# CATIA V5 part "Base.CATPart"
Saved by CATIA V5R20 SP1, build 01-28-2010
Part number: Base
Bounding box of the stored display mesh (mm): x -23.876 to 23.876, y 0 to 88.9, z 0 to 54.102
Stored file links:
  D:\v5_r20\psrt_files_downloaded\c13-catia-v5r20-prt\c13-catia-v5r20-figr-13-43\Part & Asm files\Base.CATPart
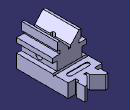
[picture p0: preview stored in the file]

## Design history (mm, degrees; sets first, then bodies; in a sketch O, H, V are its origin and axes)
Body1 (main body)
  Sketch1 on xy-plane, origin (0, 0, 0), H (1, 0, 0), V (0, 1, 0)
    line L1 (-23.876, 0) -> (23.876, 0)
    point P1 (-23.876, 0)
    point P2 (23.876, 0)
    construction line L2 (-23.876, 50.8) -> (23.876, 50.8)
    point P3 (-23.876, 50.8)
    point P4 (23.876, 50.8)
    line L3 (23.876, 0) -> (23.876, 72.898)
    point P5 (23.876, 72.898)
    line L4 (23.876, 72.898) -> (13.462, 72.898)
    point P6 (13.462, 72.898)
    line L5 (13.462, 72.898) -> (13.462, 77.724)
    point P7 (13.462, 77.724)
    line L6 (13.462, 77.724) -> (16.51, 77.724)
    point P8 (16.51, 77.724)
    line L7 (16.51, 77.724) -> (16.51, 88.9)
    point P9 (16.51, 88.9)
    line L8 (16.51, 88.9) -> (13.462, 88.9)
    point P10 (13.462, 88.9)
    line L9 (13.462, 88.9) -> (1.778, 77.724)
    point P11 (1.778, 77.724)
    line L10 (1.778, 77.724) -> (1.778, 72.898)
    point P12 (1.778, 72.898)
    line L11 (1.778, 72.898) -> (0, 72.898)
    point P13 (0, 72.898)
    point P14 (0, 72.898)
    point P15 (-1.778, 72.898)
    line L12 (-1.778, 72.898) -> (0, 72.898)
    point P16 (-1.778, 77.724)
    line L13 (-1.778, 77.724) -> (-1.778, 72.898)
    point P17 (-13.462, 88.9)
    line L14 (-13.462, 88.9) -> (-1.778, 77.724)
    point P18 (-16.51, 88.9)
    line L15 (-16.51, 88.9) -> (-13.462, 88.9)
    point P19 (-16.51, 77.724)
    line L16 (-16.51, 77.724) -> (-16.51, 88.9)
    point P20 (-13.462, 77.724)
    line L17 (-13.462, 77.724) -> (-16.51, 77.724)
    point P21 (-13.462, 72.898)
    line L18 (-13.462, 72.898) -> (-13.462, 77.724)
    point P22 (-23.876, 72.898)
    line L19 (-23.876, 72.898) -> (-13.462, 72.898)
    point P23 (-23.876, 50.8)
    point P24 (23.876, 50.8)
    construction line L20 (23.876, 50.8) -> (-23.876, 50.8)
    point P25 (-23.876, 0)
    line L21 (-23.876, 0) -> (-23.876, 72.898)
    length L1 = 47.752
    distance P2 V = 23.876
    distance L2 L1 = 50.8
    distance P5 L2 = 22.098
    distance L7 P1 = 40.386
    distance L5 P1 = 37.338
    distance L2 P7 = 26.924
    distance P9 L2 = 38.1
    distance P10 L3 = 10.414
    distance L10 L3 = 22.098
    distance L11 L2 = 22.098
    distance P11 L2 = 26.924
    horizontal: L1 H, L2 H, L4 H, L6 H, L8 H, L11 H
    coincidence: H L1, P13 V, P13 P14
    vertical: L3 V, L5 V, L7 V, L10 V
    symmetry: P13 P14 V, P12 P15 V, L11 L12 V, P11 P16 V, L10 L13 V, P10 P17 V, L9 L14 V, P9 P18 V, L8 L15 V, P8 P19 V, L7 L16 V, P7 P20 V, L6 L17 V, P6 P21 V, L5 L18 V, P5 P22 V, L4 L19 V, P4 P23 V, P3 P24 V, L2 L20 V, P2 P25 V, L3 L21 V
  Pad1: profile Sketch1, direction (0, 0, 1), length 19.05
  Sketch2 on face of Pad1, origin (23.876, 0, 0), H (0, 1, 0), V (0, 0, 1)
    point P1 (50.8, 19.05)
    line L1 (50.8, 19.05) -> (52.324, 16.4104)
    line L2 (52.324, 16.4104) -> (53.848, 19.05)
    line L3 (53.848, 19.05) -> (50.8, 19.05)
    reference projected line E1 (72.898, 19.05) -> (0, 19.05) from edge of Pad1
    length L2 = 3.048
    length L1 = 3.048
    distance P1 V = 50.8
    angle L1 L2 = 60
    horizontal: L3 H
    coincidence: L3 E1
  Pocket1: profile Sketch2, direction (-1, 0, 0), through (limit type 6)
  Sketch3 on face of Pad1, origin (0, 0, 0), H (1, 0, 0), V (0, 0, 1)
    line L1 (17.526, 19.05) -> (17.526, 31.75)
    point P1 (17.526, 19.05)
    point P2 (17.526, 31.75)
    line L2 (17.526, 31.75) -> (23.876, 31.75)
    point P3 (23.876, 31.75)
    line L3 (23.876, 31.75) -> (23.876, 38.1)
    point P4 (23.876, 38.1)
    line L4 (23.876, 38.1) -> (13.462, 38.1)
    point P5 (13.462, 38.1)
    line L5 (13.462, 38.1) -> (13.462, 42.926)
    point P6 (13.462, 42.926)
    line L6 (13.462, 42.926) -> (16.637, 42.926)
    point P7 (16.637, 42.926)
    line L7 (16.637, 42.926) -> (16.637, 54.102)
    point P8 (16.637, 54.102)
    reference projected line E1 (23.876, 19.05) -> (-23.876, 19.05) from edge of Pad1
    reference projected line E2 (23.876, 0) -> (23.876, 19.05) from edge of Pad1
    reference projected line E3 (-23.876, 19.05) -> (-23.876, 0) from edge of Pad1
    line L8 (16.637, 54.102) -> (13.462, 54.102)
    point P9 (13.462, 54.102)
    point P10 (1.651, 41.402)
    line L9 (1.651, 41.402) -> (1.651, 38.1)
    point P11 (1.651, 38.1)
    line L10 (1.651, 38.1) -> (0, 38.1)
    point P12 (0, 38.1)
    line L11 (1.651, 41.402) -> (13.462, 54.102)
    point P13 (-13.462, 54.102)
    point P14 (-1.651, 41.402)
    line L12 (-1.651, 41.402) -> (-13.462, 54.102)
    point P15 (0, 38.1)
    point P16 (-1.651, 38.1)
    line L13 (-1.651, 38.1) -> (0, 38.1)
    line L14 (-1.651, 41.402) -> (-1.651, 38.1)
    point P17 (-16.637, 54.102)
    line L15 (-16.637, 54.102) -> (-13.462, 54.102)
    point P18 (-16.637, 42.926)
    line L16 (-16.637, 42.926) -> (-16.637, 54.102)
    point P19 (-13.462, 42.926)
    line L17 (-13.462, 42.926) -> (-16.637, 42.926)
    point P20 (-13.462, 38.1)
    line L18 (-13.462, 38.1) -> (-13.462, 42.926)
    point P21 (-23.876, 38.1)
    line L19 (-23.876, 38.1) -> (-13.462, 38.1)
    point P22 (-23.876, 31.75)
    line L20 (-23.876, 31.75) -> (-23.876, 38.1)
    point P23 (-17.526, 31.75)
    line L21 (-17.526, 31.75) -> (-23.876, 31.75)
    point P24 (-17.526, 19.05)
    line L22 (-17.526, 19.05) -> (-17.526, 31.75)
    line L23 (-17.526, 19.05) -> (17.526, 19.05)
    distance V L1 = 17.526
    distance L2 H = 31.75
    distance L4 H = 38.1
    distance L6 H = 42.926
    distance L7 V = 16.637
    distance L5 E3 = 37.338
    distance V P9 = 13.462
    distance L8 H = 54.102
    distance L9 V = 1.651
    length L9 = 3.302
    vertical: L1 V, L3 V, L5 V, L7 V, L9 V
    horizontal: L2 H, L4 H, L6 H, L8 H, L10 H, L23 H
    coincidence: P1 E1, L3 E2, P11 L4, P12 V, P12 P15
    symmetry: P9 P13 V, P10 P14 V, L11 L12 V, P12 P15 V, P11 P16 V, L10 L13 V, L9 L14 V, P8 P17 V, L8 L15 V, P7 P18 V, L7 L16 V, P6 P19 V, L6 L17 V, P5 P20 V, L5 L18 V, P4 P21 V, L4 L19 V, P3 P22 V, L3 L20 V, P2 P23 V, L2 L21 V, P1 P24 V, L1 L22 V
  Pad2: profile Sketch3, direction (0, 1, 0), length 50.8
  Sketch4 on face of Pad1, origin (4.0235, 27.8102, 0), H (1, 0, 0), V (0, -1, 0)
    point P1 (-4.0235, 2.4102)
    reference projected line E1 (13.5025, -22.9898) -> (-21.5495, -22.9898) from edge of Pad2
    reference intersected line E2 through (-4.0235, 0) direction (0, 1) from yz-plane
    distance P1 E1 = 25.4
    coincidence: E2 P1
  Hole1: placed by Sketch4, at (0, 25.4, 0) direction (0, 0, 1), diameter 7.874, depth 54.102
  Sketch5 on face of Pad2, origin (17.526, 12.3932, 23.5222), H (0, 1, 0), V (0, 0, 1)
    point P1 (13.0068, 1.8778)
    reference projected line E1 (-12.3932, 8.2278) -> (-12.3932, -4.4722) from edge of Pad2
    reference projected line E2 (-12.3932, -23.5222) -> (60.5048, -23.5222) from edge of Pad1
    distance E1 P1 = 25.4
    distance E2 P1 = 25.4
  Hole2: placed by Sketch5, at (17.526, 25.4, 25.4) direction (-1, 0, 0), diameter 9.652, depth 54.102
  Sketch6 on face of Pad1, origin (0, 0, 19.05), H (1, 0, 0), V (0, 1, 0)
    construction line L1 (-23.876, 63.373) -> (23.876, 63.373)
    point P1 (-23.876, 63.373)
    point P2 (23.876, 63.373)
    reference projected line E1 (23.876, 53.848) -> (-23.876, 53.848) from edge of Pocket1
    construction line L2 (-12.7, 63.373) -> (12.7, 63.373)
    point P3 (-12.7, 63.373)
    line L3 (-12.7, 66.548) -> (12.7, 66.548)
    line L4 (12.7, 60.198) -> (-12.7, 60.198)
    arc A1 centre (12.7, 63.373) radius 3.175 from (12.7, 66.548) to (12.7, 60.198) cw
    arc A2 centre (-12.7, 63.373) radius 3.175 from (-12.7, 60.198) to (-12.7, 66.548) cw
    reference projected line E2 (23.876, 72.898) -> (23.876, 0) from edge of Pad1
    reference projected line E3 (-23.876, 72.898) -> (-23.876, 0) from edge of Pad1
    reference projected line E4 (-23.876, 72.898) -> (-23.876, 0) from edge of Pad1
    distance E1 L1 = 9.525
    radius A1 = 3.175
    distance A1 A2 = 31.75
    distance P3 E4 = 11.176
    horizontal: L1 H, L2 H
    coincidence: P3 L1, P2 E2, P1 E3
    tangency: A1 L3, A2 L3, A1 L4, A2 L4
    parallelism: L2 L3
  Pocket2: profile Sketch6, direction (0, 0, -1), length 0.762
